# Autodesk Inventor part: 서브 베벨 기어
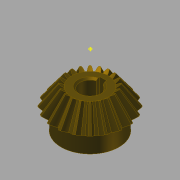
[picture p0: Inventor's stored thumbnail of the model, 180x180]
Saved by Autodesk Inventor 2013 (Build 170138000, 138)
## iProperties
Created: 2014-10
Part Number: 서브 베벨 기어
Material: 강철, 탄소
Document SubType Name: Modeling
Designer: KYOUNG IL JANG
Categories: <?xml version="1.0" encoding="UTF-16"?> <MemberInstance><Categories><FamilyTemplate><FamilyTemplateParameter ValueType="xs:double" Id="1" ObjectReferenceKey="da
Mass: 135.037 g
Surface Area: 63.6518 cm^2
Volume: 17.1585 cm^3
Density: 7.87 g/cm^3
CustomPartVersion: 1
Author: SeoGD™ [www.esajin.kr]
Revision Number: 1
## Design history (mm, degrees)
node "맨 위 점"
node "메쉬 평면2"
sketch "톱니 본체 스케치"
  geometry: L1 (0, 0)-(18.003, -31.331); L2 (18.003, -31.331)-(21.664, -28.891); L3 (21.664, -28.891)-(0, 0); L4 (20, -30)-(0, 0); L5 (10.813, -18.818)-(13.012, -17.352); L6 (18.003, -31.331)-(10.813, -18.818); L7 (21.664, -28.891)-(13.012, -17.352); L8 (0, -39.387)-(0, 6.564) reference; L9 (0, -30)-(21.664, -30)
  constraints: 16 end point, 4 point on line, 3 perpendicular, 2 collinear, 1 horizontal alignment, 1 vertical alignment
  dimensions: "d0" = 40 diameter of L4.start L8 (= da_de); "d1" = 36.00616 diameter of L1.end L8 (= da_dfe); "d2" = 43.3282 diameter of L2.end L8 (= da_dae); "d3" = 14.4 distance between parallel lines of L2 L5 (= da_b); "d4" = 28.8906 vertical distance of L2.end L1.start (= da_ve)
revolve "톱니 본체" sketch "톱니 본체 스케치" stored, may be unused: angle "d5" = 90 deg
node "시작점"
node "톱니 평면"
sketch "시작 스케치"
  geometry: L1 (0, -23.505)-(0, 10.645) reference; L2 (-0.834, -2.928)-(0.834, -2.928); A1 r 8.898 centre (-9.698, -3.713) between (-0.834, -2.928) and (-3.903, 3.04); A2 r 8.898 centre (9.698, -3.713) between (3.903, 3.04) and (0.834, -2.928); A3 r 27.357 centre (0, -24.037) between (3.903, 3.04) and (-3.903, 3.04); 1 further point
  constraints: 6 point on circle, 3 centre point, 3 symmetric about line, 2 end point, 1 coincident, 1 perpendicular, 1 other
  dimensions: "d7" = 8.89846 radius of A1 (= fd_rr); "d8" = 9.69794 horizontal distance of point (0, -24.037) A1.centre (= fd_x); "d9" = 20.32439 vertical distance of point (0, -24.037) A1.centre (= fd_y); "d57" = 27.35701 radius of A3 (= 0.5 x fd_dva + 0.3 x da_he); "d58" = 21.10901 distance from line of A3.centre L2 (= 0.5 x fd_dva - 1.12 x da_he)
node "끝점"
  node "끝 평면"
sketch "3D 스케치 오른쪽"
  node "Helical Curve Right" dims "d65" = 229.90621 (computed from da_dm, da_delta, da_beta), "d66" = 31.5, "d67" = 40 (= da_de), "d68" = -5.88003 (= -da_delta), "d69" = 12.16458 (computed from fd_loft, da_delta)
node "끝 평면 오른쪽"
sketch "끝 스케치 오른쪽"
  geometry: L1 (0, -22.649)-(0, 12.15) reference; L2 (-0.497, -1.72)-(0.497, -1.72); A1 r 5.299 centre (-5.775, -2.187) between (-0.497, -1.72) and (-2.324, 1.834); A2 r 5.299 centre (5.775, -2.187) between (2.324, 1.834) and (0.497, -1.72); A3 r 16.291 centre (0, -14.29) between (2.324, 1.834) and (-2.324, 1.834); 1 further point
  constraints: 6 point on circle, 3 centre point, 3 symmetric about line, 2 end point, 1 coincident, 1 perpendicular, 1 other
  dimensions: "d70" = 5.77526 horizontal distance of A3.centre A1.centre (computed from fd_x, fd_ratio); "d71" = 12.10346 vertical distance of point (0, -14.29) A1.centre (computed from fd_y, fd_ratio); "d72" = 5.29916 radius of A1 (computed from fd_rr, fd_ratio); "d73" = 12.57071 distance from line of point (0, -14.29) L2 (computed from d58, fd_ratio); "d74" = 16.29149 radius of A3 (computed from d57, fd_ratio)
feature "로프트 오른쪽" sketch "끝 스케치 오른쪽" dims "d75" = 0, "d77" = 0, "d79" = 0, "d80" = 90 deg, "d85" = 20, "d92" = 90 deg, "d93" = 90 deg, "da_teethtype" = 0 [user parameter]
sketch "3D 스케치 왼쪽"
  node "Helical Curve Left" dims "d26" = 229.90621 (computed from da_dm, da_delta, da_beta), "d27" = 12.16458 (computed from fd_loft, da_delta), "d28" = 40 (= da_de), "d29" = -5.88003 (= -da_delta)
node "끝 평면 왼쪽"
sketch "끝 스케치 왼쪽" dims "d56" = 10.82768 (derived)
  geometry: L1 (0, -35.087)-(0, 18.089) reference; L2 (-0.497, -1.716)-(0.497, -1.716); A1 r 5.299 centre (-5.775, -2.183) between (-0.497, -1.716) and (-2.324, 1.838); A2 r 5.299 centre (5.775, -2.183) between (2.324, 1.838) and (0.497, -1.716); A3 r 16.291 centre (0, -14.287) between (2.324, 1.838) and (-2.324, 1.838); 2 further points; 1 other entity
  constraints: 6 point on circle, 3 centre point, 3 symmetric about line, 2 end point, 1 coincident, 2 other
  dimensions: "d30" = 5.29916 radius of A1 (computed from fd_rr, fd_ratio); "d31" = 5.77526 horizontal distance of point (0, -14.287) A1.centre (computed from fd_x, fd_ratio); "d32" = 12.10346 vertical distance of A1.centre point (0, -14.287) (computed from fd_y, fd_ratio); "d61" = 16.29149 radius of A3 (computed from d57, fd_ratio); "d62" = 12.57071 distance from line of point (0, -14.287) L2 (computed from d58, fd_ratio)
feature "로프트 왼쪽" sketch "끝 스케치 왼쪽" dims "d35" = 0, "d37" = 0, "d39" = 0, "d40" = 90 deg, "d84" = 10, "d90" = 90 deg, "d91" = 90 deg, "da_teethtype" = 0 [user parameter]
sketch "본체 스케치"
  geometry: L1 (0, -35.038)-(0, -19.531) reference; L2 (18.003, -31.331)-(10.813, -18.818) reference; L3 (10.813, -18.818)-(0, -18.818); L4 (18.003, -31.331)-(0, -31.331)
  constraints: 4 end point, 2 perpendicular, 2 point on line
revolve "본체 고정" sketch "본체 스케치" stored, may be unused: angle "d46" = 90 deg
feature "피치 지름" dims angle "d47" = 90 deg
sketch "스케치8"
  geometry: C1 r 17 at (0, 0); 1 further point
  constraints: 1 centre point, 1 coincident
  dimensions: "d94" = 34 diameter of C1
extrude "돌출1" join sketch "스케치8" distance "d95" = 10; taper "d96" = 0 deg
sketch "스케치9"
  geometry: 1 further point
hole "구멍1" sketch "스케치9" at (0, 0) diameter "d97" = 12; stored, may be unused: countersink angle "d101" = 90 deg, drill point angle "d103" = 118 deg; dims "d98" = 6, "d99" = 4, "d100" = 2, "d102" = 8
sketch "스케치10"
  geometry: 1 further point
sketch "스케치11"
  geometry: 1 further point
sketch "스케치12"
  geometry: L1 (-2, 5.657)-(-2, 7.8); L2 (-2, 7.8)-(2, 7.8); L3 (2, 7.8)-(2, 5.657); A1 r 6 centre (0, 0) between (-2, 5.657) and (2, 5.657) reference; 1 further point
  constraints: 6 end point, 2 parallel, 2 point on circle, 1 perpendicular, 1 vertical
  dimensions: "d104" = 4 distance of L1.end L2.end; "d105" = 13.8 dimension on A1 L2
extrude "돌출2" cut sketch "스케치12" stored distance "d106" = 7; taper "d107" = 0 deg
chamfer "모따기1" distance "d108" = 1; stored, may be unused: second distance "d109" = 2, angle "d110" = 45 deg
body "Solid1"
feature "로프트" dims "d17" = 0, "d18" = 90 deg, "d19" = 0, "d20" = 90 deg, "d89" = 0, "da_teethtype" = 0 [user parameter]
pattern_circular "원형 패턴" dims angle "d22" = 360 deg, "d88" = 0, "da_teethtype" = 0 [user parameter]
pattern_circular "원형 패턴 오른쪽" dims angle "d82" = 360 deg, "da_teethtype" = 0 [user parameter]
pattern_circular "원형 패턴 왼쪽" dims angle "d42" = 360 deg, "da_teethtype" = 0 [user parameter]
sketch "끝 스케치"
  geometry: L1 (0, -15.359)-(0, 6.983) reference; L2 (-0.497, -1.72)-(0.497, -1.72); A1 r 5.299 centre (-5.775, -2.187) between (-0.497, -1.72) and (-2.324, 1.834); A2 r 5.299 centre (5.775, -2.187) between (2.324, 1.834) and (0.497, -1.72); A3 r 16.291 centre (0, -14.29) between (2.324, 1.834) and (-2.324, 1.834); 1 further point
  constraints: 6 point on circle, 3 centre point, 3 symmetric about line, 2 end point, 1 coincident, 1 other
  dimensions: "d12" = 5.29916 radius of A1 (computed from fd_rr, fd_ratio); "d15" = 5.77526 horizontal distance of A1.centre point (0, -14.29) (computed from fd_x, fd_ratio); "d16" = 12.10346 vertical distance of A1.centre point (0, -14.29) (computed from fd_y, fd_ratio); "d59" = 16.29149 radius of A3 (computed from d57, fd_ratio); "d60" = 12.57071 distance from line of A3.centre L2 (computed from d58, fd_ratio)
sketch "Sketch6"
  geometry: L1 (20, -30)-(0, 0) reference; L2 (0, -37.8)-(0, 6.3) reference
body "Srf1"
other parameters: "da_b" = 14.4 [user parameter; used in 2 equation terms], "da_de" = 40 [user parameter; used in 4 equation terms], "da_dae" = 43.3282 [user parameter; used in 2 equation terms], "da_dfe" = 36.00616 [user parameter; used in 1 equation term], "da_le" = 36.05551 [user parameter; used in 1 equation term], "da_omega" = 90 deg [user parameter; used in 1 equation term], "da_beta" = 0 [user parameter; used in 2 equation terms], "da_delta" = 5.88003 [user parameter; used in 8 equation terms], "da_alpha" = 20 deg [user parameter; used in 2 equation terms], "da_he" = 4.4 [user parameter; used in 4 equation terms], "da_ve" = 28.8906 [user parameter; used in 1 equation term], "fd_dv" = 48.07402 (computed from da_de, da_delta) [user parameter; used in 1 equation term], "fd_dva" = 52.07402 (computed from da_dae, da_delta) [user parameter; used in 3 equation terms], "fd_dvb" = 45.1748 (computed from fd_dv, da_alpha) [user parameter; used in 2 equation terms], "da_zv" = 240.37008 [user parameter; used in 1 equation term], "fd_loft" = 14.62 (= da_b + 0.05 x da_he) [user parameter; used in 4 equation terms], "fd_ratio" = 5.95514 (computed from da_le, fd_loft) [user parameter; used in 15 equation terms], "fd_rr" = 8.89846 (computed from fd_dd, fd_dvb) [user parameter; used in 6 equation terms], "fd_angle" = 0.66075 (computed from da_zv) [user parameter; used in 4 equation terms], "fd_x1" = 1.58709 (computed from da_dvw, fd_angle) [user parameter; used in 1 equation term], "fd_y1" = 23.98456 (computed from da_dvw, fd_angle) [user parameter; used in 1 equation term], "fd_x2" = 8.11084 (computed from fd_rr, fd_angle2, fd_angle) [user parameter; used in 1 equation term], "fd_y2" = 3.66016 (computed from fd_rr, fd_angle2, fd_angle) [user parameter; used in 1 equation term], "fd_x" = 9.69794 (= fd_x1 + fd_x2) [user parameter; used in 4 equation terms], "fd_y" = 20.32439 (= fd_y1 - fd_y2) [user parameter; used in 4 equation terms], "fd_angle2" = 3.57832 (computed from fd_dvb, fd_dd, da_alpha) [user parameter; used in 2 equation terms], "fd_dd" = 48.55402 (= fd_dva - 0.8 x da_he) [user parameter; used in 2 equation terms], "da_dvw" = 48.07402 [user parameter; used in 2 equation terms], "d11" = 14.62 (= fd_loft), "da_dm" = 32.01232 [user parameter; used in 2 equation terms], "da_x" = 0 [user parameter], "da_m" = 2 [user parameter], "d48" = 0, "d49" = 0, "d50" = 90 deg (= da_omega), "d51" = 9 deg (computed from da_z), "d52" = 0, "d53" = 0, "d54" = 0
